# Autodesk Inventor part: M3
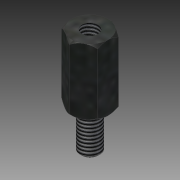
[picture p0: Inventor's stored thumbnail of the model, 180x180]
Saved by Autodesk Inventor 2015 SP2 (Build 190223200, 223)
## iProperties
Created: 2012-08
Part Number: M3
Material: Stahl
Document SubType Name: Modeling
Designer: rYan
Density: 7.85 g/cm^3
Mass: 1.74537 g
Surface Area: 3.04272 cm^2
Volume: 0.22234 cm^3
Appearance: Platte
Author: rYan
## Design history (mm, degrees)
derived "Abstandsbolzen Typ B.ipt"
feature "Volumenkörper1::Abstandsbolzen Typ B.ipt"
tag "TaggingFeature1"
body "Solid1"
other parameters: "SW" = 5.5, "d2" = 0, "l_" = 6.5, "d9" = 118 deg, "GA_" = 3, "A_" = 6, "d13" = 0, "d17" = 0.25, "d20" = 45 deg
